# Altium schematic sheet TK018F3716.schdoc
size 297 x 209 mm; Symbol: Drawing-Symbol_A4; Company: 嘉立创EDA; Version: V1.0; Page Size: A4; @Project Name: TK018F3716; @Page Count: 1; @Update Date: 2025-11-08; @Create Date: 2025-11-08; @Schematic Name: Schematic1; @Page No: 1; @Page Name: P1; Device: Drawing-Symbol_A4; @Create Time: 14:39:57; @Update Time: 14:39:57; Border: 1; Width: 1170; Height: 825; Region Start: 1; X Region Count: 6; Y Region Count: 4; Blade Width: 10; Title Block Position: 3; Title Block: 1; @Board Name: Board1
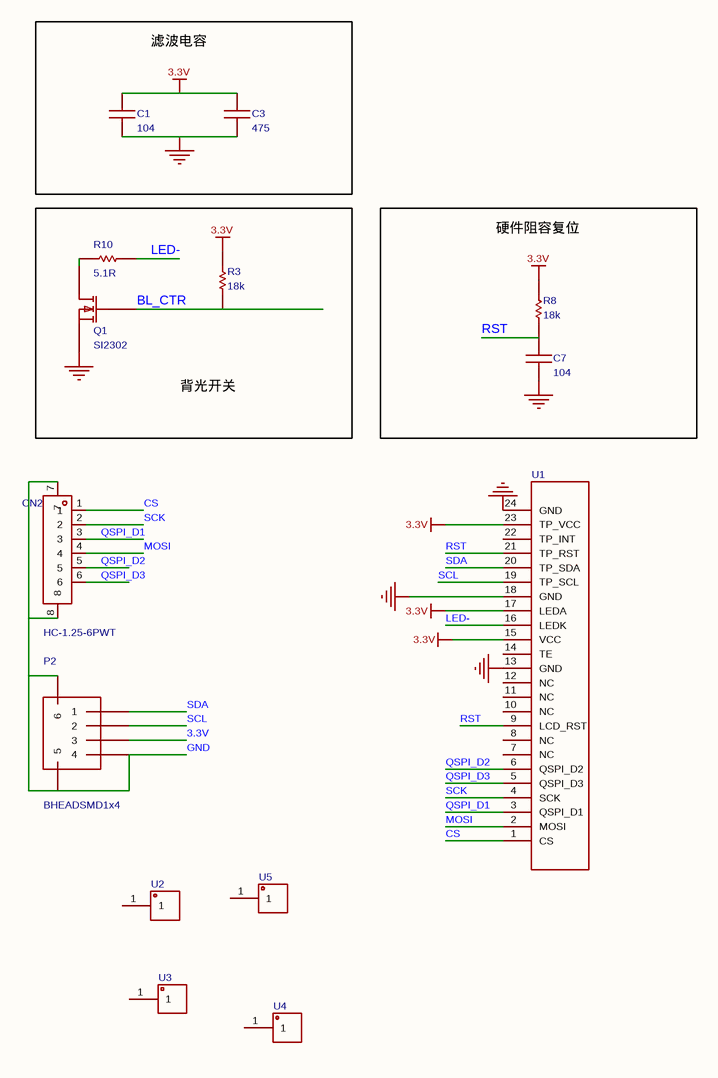
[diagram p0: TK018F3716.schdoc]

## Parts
C1  104  [C0603-1]
C3  475  [C0603-2]
C7  104  [C0603-1]
CN2  HC-1.25-6PWT  [CONN-SMD_6P-P1.25_HC-1.25-6PWT]
P2  BHEADSMD1x4  [BHEADSMD1x4]
Q1  SI2302  [SOT23A]
R3  18k  [R0603]
R8  18k  [R0603]
R10  5.1R  [R0603]
U1  (no value)  [TK014F1246-24P]
U2  (no value)  [SMTWEM2]
U3  (no value)  [SMTWEM2]
U4  (no value)  [SMTWEM2]
U5  (no value)  [SMTWEM2]

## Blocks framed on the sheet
滤波电容: C1 C3
背光开关: Q1 R3 R10
硬件阻容复位: C7 R8

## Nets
3.3V: C1.1 C3.1 P2.3 R3.1 R8.1 U1.15(VCC) U1.17(LEDA) U1.23(TP_VCC)
GND: C1.2 C3.2 C7.2 CN2.7 CN2.8 P2.4 P2.5 P2.6 Q1.2(S) U1.13(GND) U1.18(GND) U1.24(GND)
BL_CTR: Q1.1(G) R3.2
CS: CN2.1 U1.1(CS)
LED-: R10.2 U1.16(LEDK)
MOSI: CN2.4 U1.2(MOSI)
QSPI_D1: CN2.3 U1.3(QSPI_D1)
QSPI_D2: CN2.5 U1.6(QSPI_D2)
QSPI_D3: CN2.6 U1.5(QSPI_D3)
RST: C7.1 R8.2 U1.9(LCD_RST) U1.21(TP_RST)
SCK: CN2.2 U1.4(SCK)
SCL: P2.2 U1.19(TP_SCL)
SDA: P2.1 U1.20(TP_SDA)
NetQ1_3: Q1.3(D) R10.1

Not connected (* = marked no-connect by the designer): U1 7(NC) 8(NC) 10(NC) 11(NC) 12(NC) 14(TE) 22(TP_INT); U2 1; U3 1; U4 1; U5 1

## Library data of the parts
C1 C7 = 104: Symbol: cap; Origin Footprint 2: C0402-2; Origin Footprint 3: C0402-3; Origin Footprint 5: C0603-2; Origin Footprint 6: C0603-3; Origin Footprint 7: C0805-1; Origin Footprint 8: C0805-2; Origin Footprint 9: C0805-3; Origin Footprint 10: Case B 3528; AddInBom: yes
C3 = 475: Symbol: cap; Origin Footprint 2: C0402-1; Origin Footprint 3: C0402-2; Origin Footprint 4: C0402-3; Origin Footprint 5: C0603-1; Origin Footprint 6: C0603-3; Origin Footprint 7: C0805-1; Origin Footprint 8: C0805-2; Origin Footprint 9: C0805-3; Origin Footprint 10: Case B 3528; AddInBom: yes
CN2 = HC-1.25-6PWT: 插针结构:1x6P;间距:1.25mm;安装方式:卧贴;参考系列:PicoBlade(MX 1.25);总PIN数:6P;排数:1;每排PIN数:6;行距:-;额定电流:1A;触头材质:黄铜;触头镀层:锡;工作温度:-40℃~+105℃;; Manufacturer: HCTL(华灿天禄); Pins Structure: 1x6P; Pitch: 1.25mm; Number of PINs Per Row: 6; Current Rating: 1A; Voltage Rating: 125V; Plastic Material: LCP; Flame Retardant Rating: UL94V-0; Supplementary Features: 辅助焊脚; Z-Height of the Board: 3.57mm; X-Length of Bottom Edge on Board (Spacing Line): 12.55mm; Y-Width of Bottom Edge on Board: 5.25mm; 3D Model: 759c9ac0920b4c9fa15d606e27a3b4ef; 3D Model Transform: 496.062,206.693,0,0,0,0,-0.002,-31.294,0; AddInBom: yes
P2 = BHEADSMD1x4: AddInBom: yes
Q1 = SI2302: Symbol: MOSFET-N; AddInBom: yes
R3 R8 R10 = 100k: Symbol: Resistor; AddInBom: yes
U1 = TK018F3716: AddInBom: yes
U2-U5 = SMTWEM2: AddInBom: yes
